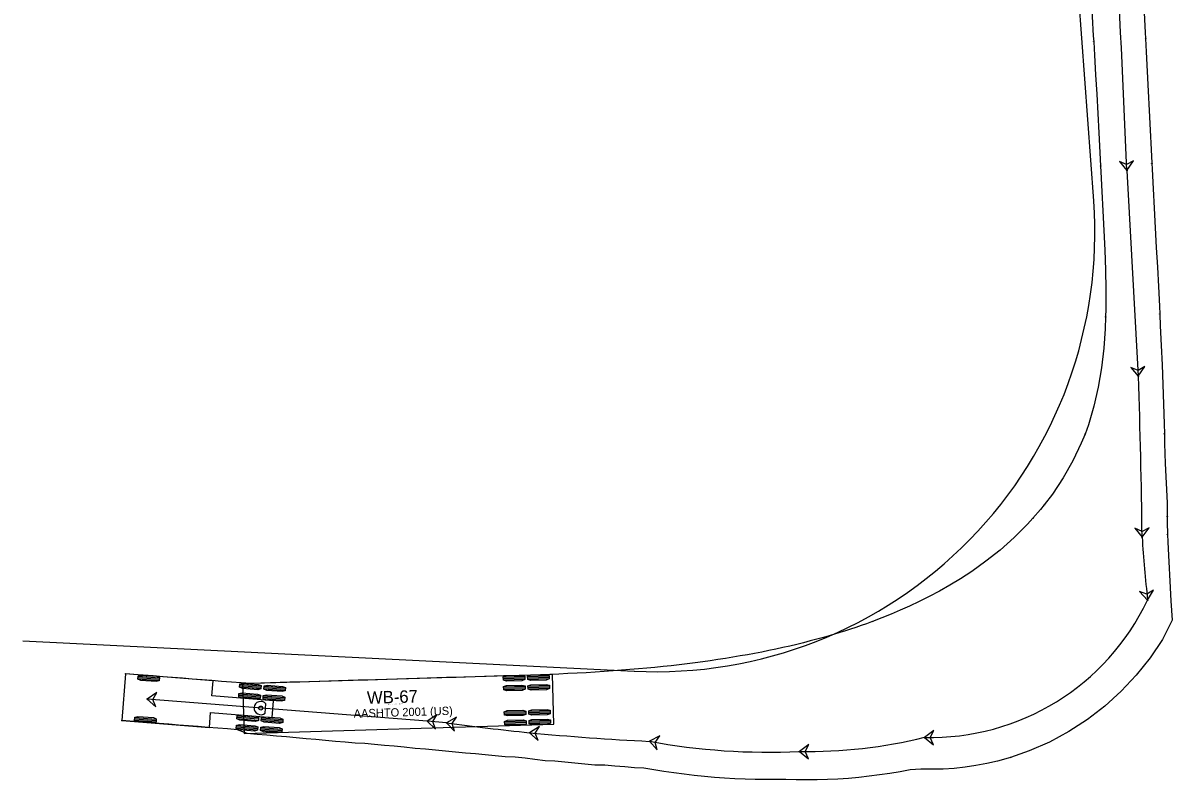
# Model space of a CAD drawing. Extents: x 2131049 to 2132623, y 643184 to 644993.
# Drawn here: x 2131048.9 to 2131245.3, y 643183.9 to 643313.3 of the extents above; entities that cross this region are included whole.
import ezdxf

# ---------------------------------------------------------------- set-up
doc = ezdxf.new("R2010")
doc.units = 0
doc.layers.add('Prop Dimension Text', color=7, linetype='Continuous')
doc.layers.add('Prop EOT', color=7, linetype='Continuous')

msp = doc.modelspace()

# ---------------------------------------------------------------- linework, layer by layer
at = {"layer": 'Prop Dimension Text'}
for p, q in [((2131237.55, 643288.06), (2131239.51, 643252.9)), ((2131066.42, 643202.06), (2131065.79, 643194.09)), ((2131081.38, 643200.88), (2131066.42, 643202.06)), ((2131068.55, 643201.43), (2131072.2, 643201.15)), ((2131068.56, 643201.66), (2131072.22, 643201.38)), ((2131139.38, 643201.96), (2131086.41, 643200.38)), ((2131130.98, 643201.48), (2131134.64, 643201.59)), ((2131135.14, 643201.6), (2131138.81, 643201.71)), ((2131135.15, 643201.37), (2131138.82, 643201.48)), ((2131139.64, 643193.46), (2131139.38, 643201.96)), ((2131068.53, 643201.21), (2131072.18, 643200.92)), ((2131081.17, 643198.32), (2131081.38, 643200.88)), ((2131085.89, 643199.83), (2131089.55, 643199.54)), ((2131085.91, 643200.06), (2131089.56, 643199.77)), ((2131085.93, 643200.29), (2131089.58, 643200)), ((2131086.41, 643200.38), (2131086.66, 643191.88)), ((2131090.04, 643199.5), (2131093.7, 643199.21)), ((2131090.06, 643199.73), (2131093.72, 643199.44)), ((2131090.08, 643199.96), (2131093.74, 643199.67)), ((2131130.99, 643201.25), (2131134.65, 643201.36)), ((2131130.99, 643201.02), (2131134.66, 643201.13)), ((2131131.03, 643199.83), (2131134.69, 643199.94)), ((2131131.03, 643199.6), (2131134.7, 643199.71)), ((2131131.04, 643199.37), (2131134.71, 643199.48)), ((2131135.16, 643201.14), (2131138.82, 643201.25)), ((2131135.19, 643199.95), (2131138.86, 643200.06)), ((2131135.2, 643199.72), (2131138.86, 643199.83)), ((2131135.21, 643199.49), (2131138.87, 643199.6)), ((2131117.94, 643194), (2131070.09, 643197.76)), ((2131091.72, 643197.48), (2131081.17, 643198.32)), ((2131085.76, 643198.18), (2131089.42, 643197.89)), ((2131085.78, 643198.41), (2131089.43, 643198.12)), ((2131085.8, 643198.64), (2131089.45, 643198.35)), ((2131089.91, 643197.85), (2131093.57, 643197.56)), ((2131089.93, 643198.08), (2131093.59, 643197.79)), ((2131089.95, 643198.31), (2131093.61, 643198.02)), ((2131091.5, 643194.62), (2131091.72, 643197.48)), ((2131090.28, 643195.35), (2131090.4, 643196.96)), ((2131131.16, 643195.55), (2131134.82, 643195.65)), ((2131135.32, 643195.67), (2131138.99, 643195.78)), ((2131135.33, 643195.44), (2131138.99, 643195.55)), ((2131065.79, 643194.09), (2131080.74, 643192.9)), ((2131065.79, 643194.09), (2131065.79, 643194.09)), ((2131067.97, 643194.14), (2131071.62, 643193.86)), ((2131067.99, 643194.37), (2131071.64, 643194.09)), ((2131068, 643194.6), (2131071.66, 643194.31)), ((2131080.74, 643192.9), (2131080.95, 643195.46)), ((2131080.95, 643195.46), (2131091.5, 643194.62)), ((2131085.46, 643194.41), (2131089.12, 643194.12)), ((2131085.48, 643194.64), (2131089.13, 643194.35)), ((2131085.5, 643194.87), (2131089.15, 643194.58)), ((2131089.61, 643194.08), (2131093.27, 643193.79)), ((2131089.63, 643194.31), (2131093.29, 643194.02)), ((2131089.65, 643194.54), (2131093.31, 643194.25)), ((2131121.24, 643193.7), (2131117.94, 643194)), ((2131131.16, 643195.32), (2131134.83, 643195.43)), ((2131131.17, 643195.09), (2131134.83, 643195.2)), ((2131131.2, 643193.9), (2131134.87, 643194.01)), ((2131131.21, 643193.67), (2131134.88, 643193.78)), ((2131131.22, 643193.44), (2131134.88, 643193.55)), ((2131135.33, 643195.21), (2131139, 643195.32)), ((2131135.37, 643194.02), (2131139.03, 643194.13)), ((2131135.38, 643193.79), (2131139.04, 643193.9)), ((2131135.38, 643193.56), (2131139.05, 643193.67)), ((2131085.33, 643192.77), (2131088.99, 643192.48)), ((2131085.35, 643193), (2131089, 643192.71)), ((2131085.37, 643193.22), (2131089.02, 643192.93)), ((2131086.66, 643191.88), (2131139.64, 643193.46)), ((2131086.66, 643191.88), (2131086.66, 643191.88)), ((2131089.48, 643192.44), (2131093.14, 643192.15)), ((2131089.5, 643192.67), (2131093.16, 643192.38)), ((2131089.52, 643192.89), (2131093.18, 643192.6))]:
    msp.add_line(p, q, dxfattribs=at)
for points in [[(2131228.83, 643357.2), (2131229.05, 643354.22), (2131229.28, 643350.9), (2131229.51, 643347.58), (2131229.73, 643344.26), (2131229.95, 643340.94), (2131230.17, 643337.62), (2131230.38, 643334.31), (2131230.59, 643330.99), (2131230.8, 643327.67), (2131231.01, 643324.35), (2131231.21, 643321.03), (2131231.42, 643317.71), (2131231.62, 643314.39), (2131231.82, 643311.07), (2131231.88, 643310.07)], [(2131237.7, 643357.99), (2131237.93, 643355), (2131238.18, 643351.66), (2131238.43, 643348.33), (2131238.66, 643345), (2131238.89, 643341.66), (2131239.12, 643338.33), (2131239.34, 643335), (2131239.55, 643331.66), (2131239.75, 643328.33), (2131239.95, 643324.99), (2131240.15, 643321.65), (2131240.34, 643318.32), (2131240.52, 643314.98), (2131240.69, 643311.65), (2131240.74, 643310.64)], [(2131231.88, 643310.07), (2131232.02, 643307.75), (2131232.21, 643304.43), (2131232.4, 643301.11), (2131232.59, 643297.79), (2131232.77, 643294.47), (2131232.94, 643291.15), (2131233.06, 643288.82)], [(2131240.74, 643310.64), (2131240.86, 643308.31), (2131241.03, 643304.97), (2131241.19, 643301.63), (2131241.35, 643298.3), (2131241.52, 643294.96), (2131241.69, 643291.62), (2131241.82, 643289.29)], [(2131233.06, 643288.82), (2131233.11, 643287.83), (2131233.28, 643284.5), (2131233.45, 643281.16), (2131233.61, 643277.8), (2131233.77, 643274.45), (2131233.89, 643271.1), (2131233.95, 643267.74), (2131233.94, 643264.39), (2131233.91, 643263.05)], [(2131241.82, 643289.29), (2131241.87, 643288.29), (2131242.04, 643284.95), (2131242.22, 643281.61), (2131242.4, 643278.26), (2131242.58, 643274.91), (2131242.76, 643271.57), (2131242.94, 643268.22), (2131243.11, 643264.87), (2131243.18, 643263.53)], [(2131233.91, 643263.05), (2131233.83, 643261.03), (2131233.6, 643257.69), (2131233.22, 643254.36), (2131232.67, 643251.05), (2131231.93, 643247.79), (2131230.97, 643244.59), (2131230.4, 643243.02)], [(2131243.18, 643263.53), (2131243.27, 643261.53), (2131243.42, 643258.18), (2131243.56, 643254.83), (2131243.69, 643251.47), (2131243.8, 643248.12), (2131243.91, 643244.75), (2131243.96, 643243.07)], [(2131230.4, 643243.02), (2131229.77, 643241.48), (2131228.34, 643238.46), (2131226.69, 643235.57), (2131224.84, 643232.79), (2131223.43, 643230.93)], [(2131243.96, 643243.07), (2131244, 643241.39), (2131244.12, 643238.02), (2131244.26, 643234.66), (2131244.43, 643231.3), (2131244.45, 643228.94)], [(2131223.43, 643230.93), (2131222.8, 643230.15), (2131221.49, 643228.64)], [(2131244.45, 643228.94), (2131244.42, 643227.93), (2131244.48, 643225.91)], [(2131221.49, 643228.64), (2131220.59, 643227.66), (2131218.28, 643225.35), (2131215.88, 643223.21), (2131213.45, 643221.29), (2131211.03, 643219.55), (2131209.12, 643218.31), (2131207.29, 643217.2), (2131205.51, 643216.19), (2131203.76, 643215.26), (2131202.06, 643214.41), (2131200.41, 643213.63), (2131198.81, 643212.92), (2131197.26, 643212.26), (2131195.66, 643211.62), (2131194.1, 643211.02)], [(2131244.48, 643225.91), (2131244.55, 643224.56), (2131244.73, 643221.21), (2131244.91, 643217.87), (2131245.09, 643214.54), (2131245.27, 643211.21), (2131243.62, 643207.92), (2131241.52, 643204.78), (2131239.17, 643201.83), (2131236.59, 643199.08), (2131233.79, 643196.54), (2131230.8, 643194.24), (2131227.63, 643192.19), (2131224.31, 643190.41), (2131220.85, 643188.9), (2131217.64, 643187.78)], [(2131194.1, 643211.02), (2131193.92, 643210.96), (2131193.03, 643210.63), (2131192.14, 643210.32), (2131191.24, 643210.01), (2131190.33, 643209.7), (2131189.44, 643209.42), (2131188.52, 643209.13), (2131187.6, 643208.85), (2131186.67, 643208.57), (2131185.68, 643208.29), (2131184.56, 643207.98), (2131183.43, 643207.68), (2131182.3, 643207.39), (2131181.12, 643207.1), (2131179.94, 643206.82), (2131178.75, 643206.55), (2131177.56, 643206.29), (2131176.35, 643206.04), (2131175.14, 643205.79), (2131173.92, 643205.56), (2131172.69, 643205.33), (2131171.46, 643205.12), (2131170.2, 643204.9), (2131168.93, 643204.7), (2131167.64, 643204.5), (2131166.36, 643204.31), (2131165.06, 643204.13), (2131163.76, 643203.96), (2131162.43, 643203.79), (2131161.06, 643203.62), (2131159.68, 643203.46), (2131158.29, 643203.31), (2131156.89, 643203.17), (2131155.48, 643203.03), (2131154.06, 643202.91), (2131152.63, 643202.78), (2131151.2, 643202.67), (2131149.73, 643202.56), (2131148.21, 643202.45), (2131146.67, 643202.35), (2131145.13, 643202.26), (2131143.58, 643202.18), (2131142.03, 643202.1), (2131140.47, 643202.03), (2131138.91, 643201.96), (2131137.34, 643201.9), (2131135.77, 643201.85), (2131134.19, 643201.8), (2131132.61, 643201.75), (2131131.02, 643201.71), (2131129.4, 643201.66), (2131127.79, 643201.61), (2131126.16, 643201.56), (2131124.53, 643201.51), (2131122.9, 643201.46), (2131121.27, 643201.42), (2131119.63, 643201.37), (2131117.99, 643201.32), (2131116.25, 643201.27), (2131114.45, 643201.21), (2131112.77, 643201.16), (2131111.11, 643201.11), (2131109.46, 643201.06), (2131107.8, 643201.01), (2131106.15, 643200.96), (2131104.49, 643200.91), (2131102.83, 643200.87), (2131101.17, 643200.82), (2131099.5, 643200.77), (2131097.84, 643200.72), (2131096.18, 643200.67), (2131094.51, 643200.62), (2131092.85, 643200.57), (2131091.18, 643200.52), (2131089.51, 643200.47), (2131087.84, 643200.42), (2131086.17, 643200.52), (2131084.5, 643200.65), (2131082.82, 643200.78), (2131081.15, 643200.91), (2131079.48, 643201.04), (2131077.8, 643201.17), (2131076.13, 643201.3), (2131074.46, 643201.43), (2131072.78, 643201.57), (2131071.11, 643201.7), (2131069.44, 643201.83), (2131067.76, 643201.96), (2131066.42, 643202.06)], [(2131217.64, 643187.78), (2131217.27, 643187.68), (2131215.45, 643187.17), (2131213.62, 643186.75), (2131211.76, 643186.39), (2131209.89, 643186.12), (2131208.02, 643185.92), (2131206.13, 643185.79), (2131204.24, 643185.75), (2131202.36, 643185.77), (2131200.53, 643185.69), (2131198.78, 643185.35), (2131197.02, 643185.05), (2131195.26, 643184.79), (2131193.49, 643184.56), (2131191.72, 643184.36), (2131189.95, 643184.2), (2131188.17, 643184.08), (2131186.39, 643183.99), (2131184.61, 643183.94), (2131182.83, 643183.93), (2131181.05, 643183.94), (2131179.26, 643184), (2131177.51, 643184.02), (2131175.77, 643184.01), (2131174.03, 643184.03), (2131172.29, 643184.08), (2131170.55, 643184.15), (2131168.81, 643184.25), (2131167.08, 643184.38), (2131165.34, 643184.53), (2131163.61, 643184.7), (2131161.88, 643184.9), (2131160.15, 643185.13), (2131158.43, 643185.38), (2131156.71, 643185.66), (2131155, 643185.96), (2131153.4, 643186), (2131151.75, 643186.16), (2131150.03, 643186.3), (2131148.31, 643186.44), (2131146.64, 643186.46), (2131144.93, 643186.62), (2131143.21, 643186.78), (2131141.5, 643186.95), (2131139.79, 643187.12), (2131138.11, 643187.21), (2131136.39, 643187.44), (2131134.69, 643187.63), (2131132.99, 643187.8), (2131131.32, 643187.87), (2131129.61, 643188.04), (2131127.9, 643188.2), (2131126.2, 643188.37), (2131124.49, 643188.53), (2131122.79, 643188.69), (2131121.09, 643188.85), (2131119.4, 643189.01), (2131117.7, 643189.17), (2131115.9, 643189.31), (2131114.05, 643189.52), (2131112.34, 643189.68), (2131110.66, 643189.83), (2131108.99, 643189.98), (2131107.31, 643190.14), (2131105.64, 643190.23), (2131103.97, 643190.38), (2131102.29, 643190.53), (2131100.61, 643190.68), (2131098.94, 643190.83), (2131097.26, 643190.98), (2131095.59, 643191.13), (2131093.91, 643191.28), (2131092.24, 643191.42), (2131090.56, 643191.57), (2131088.89, 643191.71), (2131087.21, 643191.86), (2131085.52, 643192.52), (2131083.85, 643192.66), (2131082.18, 643192.79), (2131080.51, 643192.92), (2131078.84, 643193.05), (2131077.16, 643193.19), (2131075.49, 643193.32), (2131073.82, 643193.45), (2131072.15, 643193.58), (2131070.47, 643193.72), (2131068.8, 643193.85), (2131067.13, 643193.98), (2131065.79, 643194.09)]]:
    msp.add_lwpolyline(points, dxfattribs=at)
for points in [[(2131237.55, 643288.06), (2131238.7, 643289.69), (2131237.51, 643289.06), (2131236.27, 643289.6)], [(2131239.51, 643252.9), (2131240.64, 643254.55), (2131239.46, 643253.9), (2131238.21, 643254.42)], [(2131240.15, 643225.4), (2131241.35, 643227), (2131240.14, 643226.4), (2131238.92, 643226.98)], [(2131241.08, 643214.65), (2131242.13, 643216.35), (2131240.98, 643215.65), (2131239.71, 643216.11)], [(2131068.52, 643201.15), (2131068.57, 643201.72), (2131069.09, 643201.85), (2131071.73, 643201.64), (2131072.22, 643201.43), (2131072.18, 643200.86), (2131071.65, 643200.73), (2131069.02, 643200.94)], [(2131130.99, 643200.96), (2131130.98, 643201.53), (2131131.48, 643201.72), (2131134.12, 643201.8), (2131134.64, 643201.64), (2131134.66, 643201.07), (2131134.15, 643200.88), (2131131.51, 643200.8)], [(2131135.16, 643201.09), (2131135.14, 643201.66), (2131135.65, 643201.84), (2131138.29, 643201.92), (2131138.81, 643201.77), (2131138.82, 643201.19), (2131138.32, 643201.01), (2131135.68, 643200.93)], [(2131085.89, 643199.77), (2131085.93, 643200.34), (2131086.46, 643200.47), (2131089.09, 643200.26), (2131089.59, 643200.05), (2131089.54, 643199.48), (2131089.02, 643199.35), (2131086.38, 643199.56)], [(2131090.04, 643199.44), (2131090.09, 643200.01), (2131090.61, 643200.14), (2131093.24, 643199.93), (2131093.74, 643199.72), (2131093.7, 643199.15), (2131093.17, 643199.02), (2131090.54, 643199.23)], [(2131131.04, 643199.31), (2131131.03, 643199.88), (2131131.53, 643200.07), (2131134.17, 643200.15), (2131134.69, 643199.99), (2131134.71, 643199.42), (2131134.2, 643199.23), (2131131.56, 643199.15)], [(2131135.21, 643199.44), (2131135.19, 643200.01), (2131135.7, 643200.2), (2131138.34, 643200.27), (2131138.86, 643200.12), (2131138.87, 643199.55), (2131138.36, 643199.36), (2131135.73, 643199.28)], [(2131070.09, 643197.76), (2131071.58, 643196.42), (2131071.09, 643197.68), (2131071.77, 643198.85)], [(2131085.76, 643198.13), (2131085.8, 643198.7), (2131086.33, 643198.83), (2131088.96, 643198.62), (2131089.46, 643198.41), (2131089.41, 643197.84), (2131088.89, 643197.71), (2131086.25, 643197.91)], [(2131089.91, 643197.8), (2131089.96, 643198.37), (2131090.48, 643198.5), (2131093.11, 643198.29), (2131093.61, 643198.08), (2131093.56, 643197.51), (2131093.04, 643197.38), (2131090.41, 643197.58)], [(2131131.17, 643195.03), (2131131.15, 643195.6), (2131131.66, 643195.79), (2131134.3, 643195.87), (2131134.82, 643195.71), (2131134.84, 643195.14), (2131134.33, 643194.95), (2131131.69, 643194.87)], [(2131135.34, 643195.15), (2131135.32, 643195.73), (2131135.83, 643195.91), (2131138.47, 643195.99), (2131138.98, 643195.84), (2131139, 643195.26), (2131138.49, 643195.08), (2131135.85, 643195)], [(2131067.96, 643194.09), (2131068.01, 643194.66), (2131068.53, 643194.79), (2131071.17, 643194.58), (2131071.66, 643194.37), (2131071.62, 643193.8), (2131071.09, 643193.67), (2131068.46, 643193.88)], [(2131085.46, 643194.36), (2131085.5, 643194.93), (2131086.03, 643195.06), (2131088.66, 643194.85), (2131089.16, 643194.64), (2131089.11, 643194.07), (2131088.59, 643193.93), (2131085.95, 643194.14)], [(2131089.61, 643194.03), (2131089.66, 643194.6), (2131090.18, 643194.73), (2131092.81, 643194.52), (2131093.31, 643194.31), (2131093.27, 643193.74), (2131092.74, 643193.6), (2131090.11, 643193.81)], [(2131117.94, 643194), (2131119.41, 643192.64), (2131118.94, 643193.91), (2131119.63, 643195.07)], [(2131121.24, 643193.7), (2131122.65, 643192.28), (2131122.23, 643193.56), (2131122.98, 643194.69)], [(2131131.22, 643193.38), (2131131.2, 643193.95), (2131131.71, 643194.14), (2131134.35, 643194.22), (2131134.87, 643194.06), (2131134.88, 643193.49), (2131134.38, 643193.3), (2131131.74, 643193.22)], [(2131135.38, 643193.51), (2131135.37, 643194.08), (2131135.88, 643194.26), (2131138.51, 643194.34), (2131139.03, 643194.19), (2131139.05, 643193.61), (2131138.54, 643193.43), (2131135.9, 643193.35)], [(2131085.33, 643192.71), (2131085.37, 643193.28), (2131085.9, 643193.41), (2131088.53, 643193.2), (2131089.03, 643192.99), (2131088.98, 643192.42), (2131088.46, 643192.29), (2131085.82, 643192.5)], [(2131089.48, 643192.38), (2131089.53, 643192.95), (2131090.05, 643193.08), (2131092.68, 643192.87), (2131093.18, 643192.66), (2131093.13, 643192.09), (2131092.61, 643191.96), (2131089.98, 643192.17)], [(2131135.44, 643192.01), (2131136.91, 643190.65), (2131136.44, 643191.92), (2131137.14, 643193.07)], [(2131202.96, 643191.21), (2131204.52, 643189.95), (2131203.96, 643191.19), (2131204.58, 643192.39)], [(2131155.95, 643190.54), (2131157.3, 643189.06), (2131156.94, 643190.36), (2131157.73, 643191.45)], [(2131181.59, 643188.8), (2131183.16, 643187.56), (2131182.59, 643188.79), (2131183.19, 643190)]]:
    msp.add_lwpolyline(points, close=True, dxfattribs=at)
for centre, radius in [((2131231.88, 643310.07), 0.0417), ((2131231.88, 643310.07), 0.0417), ((2131240.74, 643310.64), 0.0417), ((2131240.74, 643310.64), 0.0417), ((2131233.06, 643288.82), 0.0417), ((2131233.06, 643288.82), 0.0417), ((2131237.55, 643288.06), 0.0417), ((2131237.55, 643288.06), 0.0417), ((2131241.82, 643289.29), 0.0417), ((2131241.82, 643289.29), 0.0417), ((2131233.91, 643263.05), 0.0417), ((2131233.91, 643263.05), 0.0417), ((2131243.18, 643263.53), 0.0417), ((2131243.18, 643263.53), 0.0417), ((2131239.51, 643252.9), 0.0417), ((2131239.51, 643252.9), 0.0417), ((2131230.4, 643243.02), 0.0417), ((2131230.4, 643243.02), 0.0417), ((2131243.96, 643243.07), 0.0417), ((2131243.96, 643243.07), 0.0417), ((2131223.43, 643230.93), 0.0417), ((2131223.43, 643230.93), 0.0417), ((2131244.45, 643228.94), 0.0417), ((2131244.45, 643228.94), 0.0417), ((2131221.49, 643228.64), 0.0417), ((2131221.49, 643228.64), 0.0417), ((2131240.15, 643225.4), 0.0417), ((2131240.15, 643225.4), 0.0417), ((2131244.48, 643225.91), 0.0417), ((2131244.48, 643225.91), 0.0417), ((2131241.08, 643214.65), 0.0417), ((2131241.08, 643214.65), 0.0417), ((2131194.1, 643211.02), 0.0417), ((2131194.1, 643211.02), 0.0417), ((2131066.42, 643202.06), 0.0417), ((2131070.09, 643197.76), 0.0417), ((2131089.53, 643196.22), 0.34), ((2131065.79, 643194.09), 0.0417), ((2131117.94, 643194), 0.0417), ((2131117.94, 643194), 0.0417), ((2131121.24, 643193.7), 0.0417), ((2131121.24, 643193.7), 0.0417), ((2131135.44, 643192.01), 0.0417), ((2131135.44, 643192.01), 0.0417), ((2131155.95, 643190.54), 0.0417), ((2131155.95, 643190.54), 0.0417), ((2131202.96, 643191.21), 0.0417), ((2131202.96, 643191.21), 0.0417), ((2131181.59, 643188.8), 0.0417), ((2131181.59, 643188.8), 0.0417), ((2131217.64, 643187.78), 0.0417), ((2131217.64, 643187.78), 0.0417)]:
    msp.add_circle(centre, radius, dxfattribs=at)
for centre, radius, start, end in [((2129401.11, 643217.16), 1837.81, 2.21079, 4.83014), ((2131157.08, 643277.43), 75, 267.1687, 4.1431), ((2130193.37, 643215.02), 1046.83, 0.56857, 2.074), ((2131670.47, 643257.25), 431.5, 184.233, 185.6657), ((2131204.02, 643232.2), 41, 268.5167, 334.6661), ((2131089.53, 643196.22), 1.14, 40.4608, 310.4608), ((2131175.24, 643586.42), 396.41, 262.1712, 264.2381), ((2131178.78, 643653.09), 463.12, 264.6309, 267.1754), ((2131176.37, 643302.01), 113.33, 259.6192, 272.6366), ((2131182.91, 643273.14), 84.34, 269.1017, 283.7535)]:
    msp.add_arc(centre, radius, start, end, dxfattribs=at)
at = {"layer": 'Prop EOT'}
for p, q in [((2131231.88, 643282.85), (2131220.78, 643436.04)), ((2131048.88, 643207.69), (2131153.37, 643202.52))]:
    msp.add_line(p, q, dxfattribs=at)

# ---------------------------------------------------------------- texts
at = {"layer": 'Prop Dimension Text'}
for s, height, p in [('WB-67', 2.125, (2131107.71, 643196.93)), ('AASHTO 2001 (US)', 1.4167, (2131105.42, 643194.56)), ('(c) 2015 Transoft Solutions, Inc. All rights reserved.', 0.085, (2131111.29, 643196.82))]:
    msp.add_text(s, height=height, rotation=1.7096, dxfattribs=at).set_placement(p)

doc.saveas('drawing.dxf')
